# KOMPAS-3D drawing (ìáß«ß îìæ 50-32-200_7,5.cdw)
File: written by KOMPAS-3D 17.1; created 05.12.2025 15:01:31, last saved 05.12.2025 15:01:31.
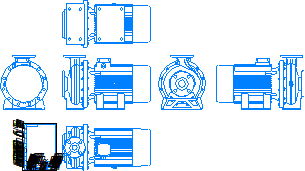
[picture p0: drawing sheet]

Sheet 1: A4, portrait

Title block, sheet 1: name: Насос МНС / 50-32-200_7,5; material: Сталь 10  ГОСТ 1050-88; mass: 156,7; sheets: 1; sheet format: A4

Views: Вид 1, Спереди, Проекционный вид 2, Проекционный вид 3, Проекционный вид 4, Проекционный вид 6
Referenced files in \\adlc.lan\data\АДЛ_ПКД\3D-модели\ADL production\Насосы ГРАНПАМП\Насосы ГРАНПАМП серии МНС\KOMPAS 3D\: Насос МНС 50-32-200_7,5.m3d
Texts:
  Andrey
  АДЛ
Dimensions and other numbers on the sheet: 1:1; 1; 50-32-200_7,5; 156,7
